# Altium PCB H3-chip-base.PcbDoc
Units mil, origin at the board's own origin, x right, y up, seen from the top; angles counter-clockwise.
Board outline 2027 x 2640 mil, 2 copper layers (Top Layer, Bottom Layer); 10 components, 44 nets, 118 pads, 31 vias.
Unrouted connection lines stored in the file: 24.
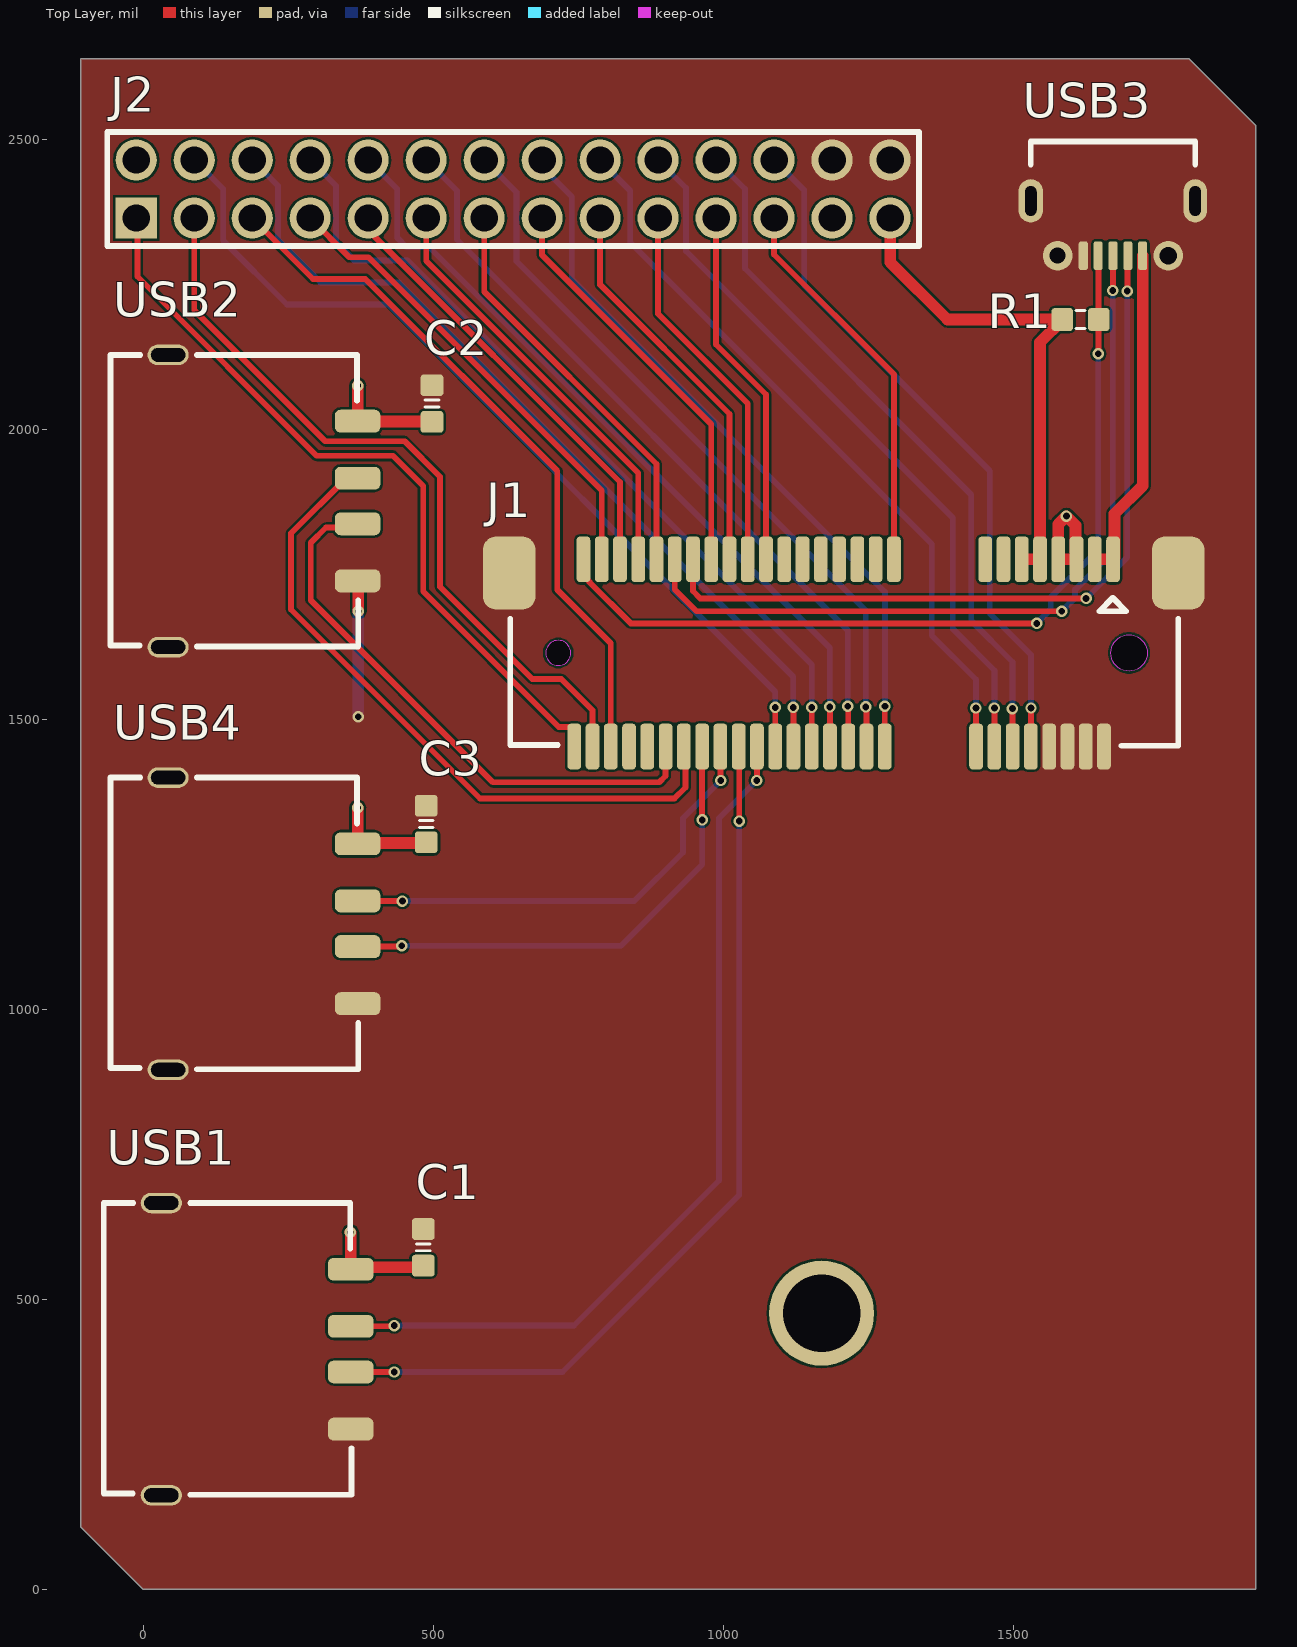
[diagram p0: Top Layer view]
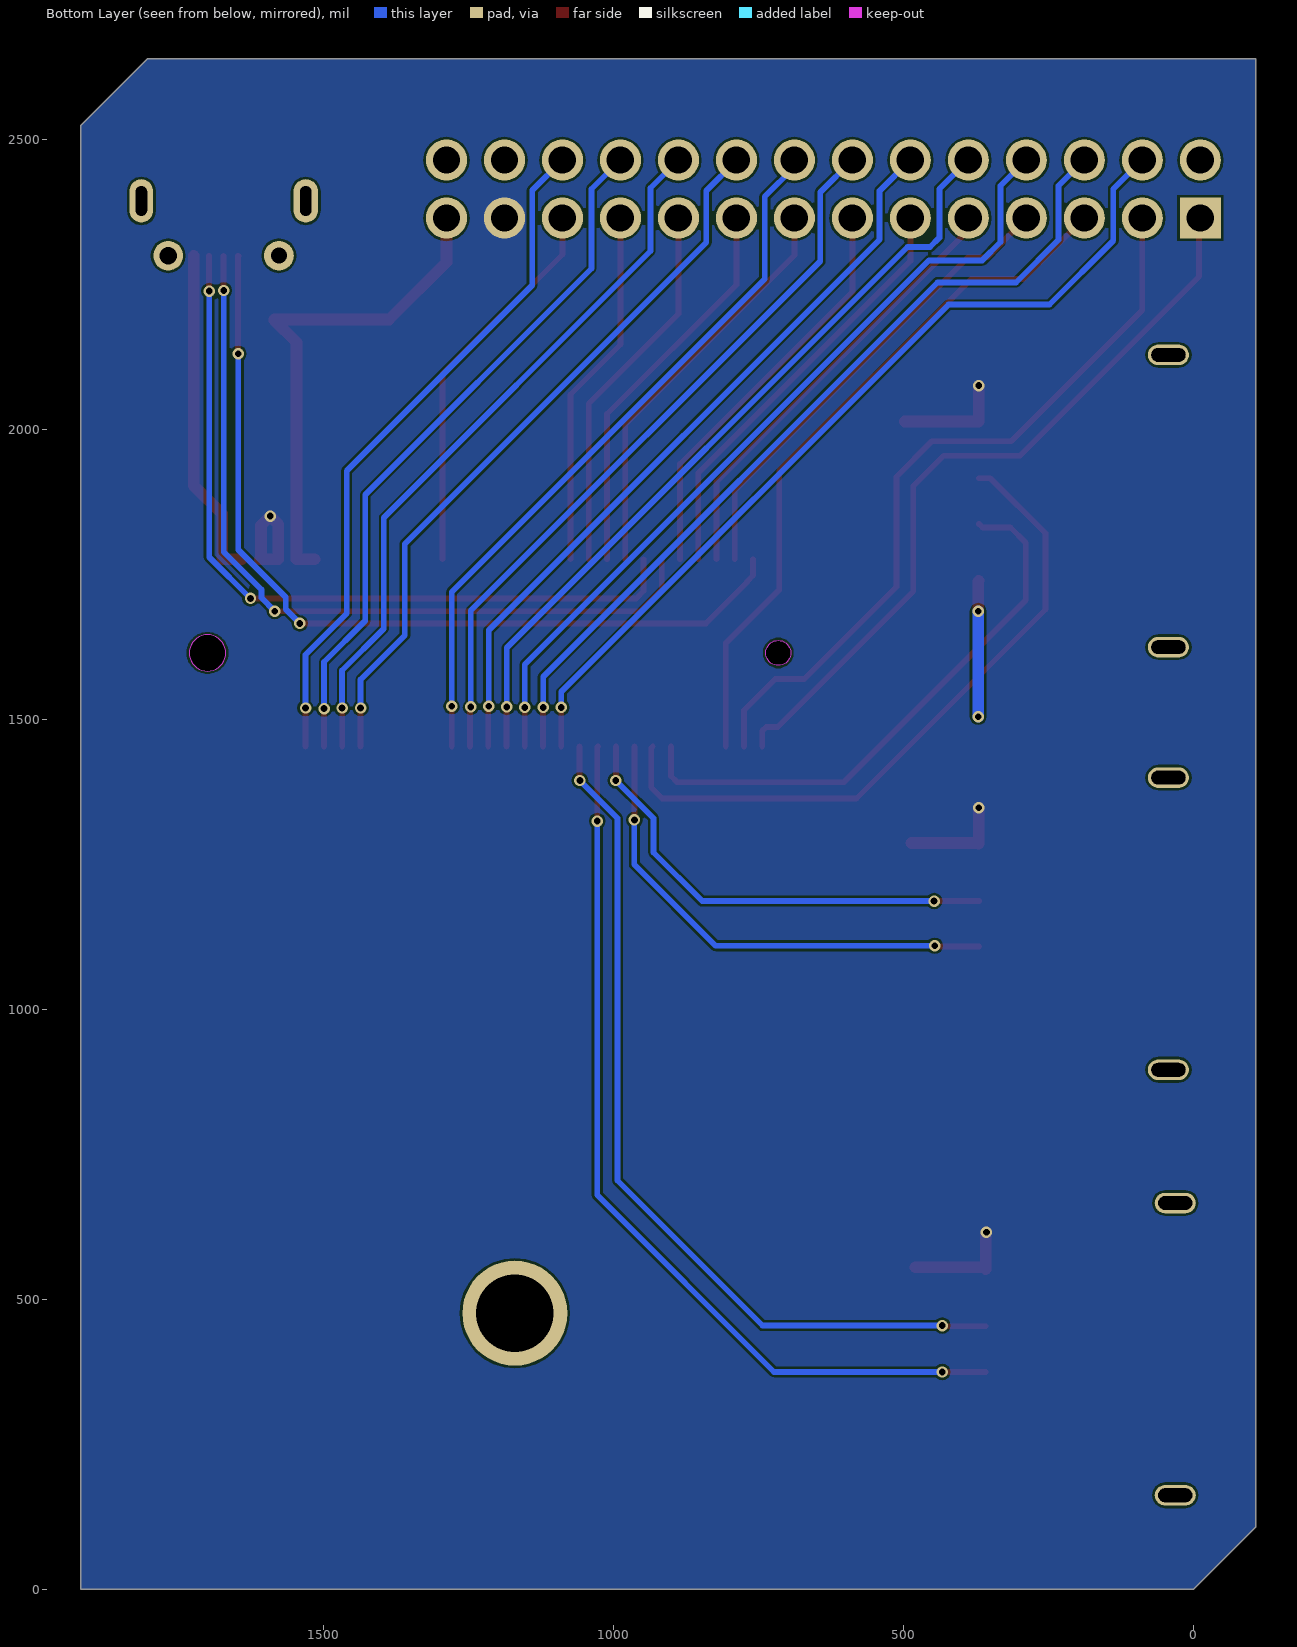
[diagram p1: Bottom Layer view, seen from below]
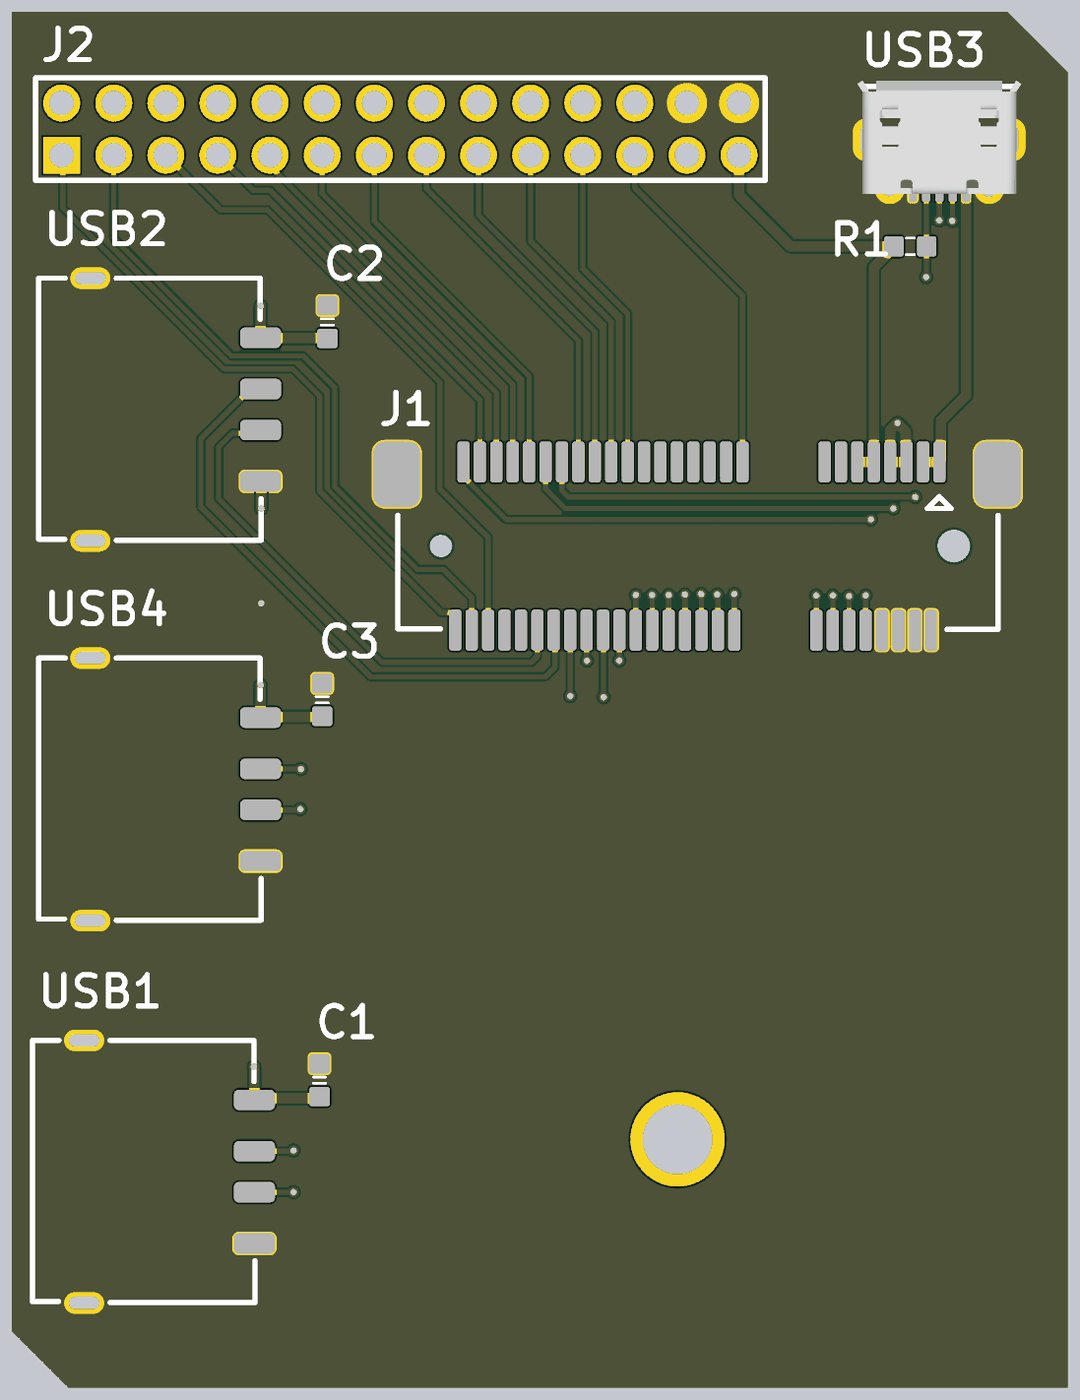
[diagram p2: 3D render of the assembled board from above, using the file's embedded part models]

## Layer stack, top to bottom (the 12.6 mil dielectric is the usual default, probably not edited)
Top Solder: solder mask 0.4, Solder Resist, Dk 3.5
Top Layer: signal copper 1.4
Dielectric 1: dielectric 12.6, FR-4, Dk 4.8
Bottom Layer: signal copper 1.4
Bottom Solder: solder mask 0.4, Solder Resist, Dk 3.5

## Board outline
-108,108 0,0 1919,0 1919,2524 1803,2640 -108,2640

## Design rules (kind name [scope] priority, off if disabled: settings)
Clearance [All] p1: gap=4 ignorepadtopadclearanceinfootprint=FALSE except(0: Arc-Hole Track-Hole SMDPad-Hole THPad-Hole Via-Hole Fill-Hole Poly-Hole Region-Hole Text-Hole)
ComponentClearance [All] p1: gap=0 collisioncheckmode=3 verticalgap=0 showdistances=FALSE
DiffPairsRouting [All] p1: maxlimit=4 minlimit=4 mostfreqgap=4 toplayer_minwidth=4 toplayer_maxwidth=4 toplayer_prefwidth=4 bottomlayer_minwidth=4 bottomlayer_maxwidth=4 bottomlayer_prefwidth=4 maxuncoupledlength=500
FanoutControl Fanout_BGA [All] p1: bgadir=Out bgaviamode=Centered fanoutstyle=Auto fanoutdirection=Alternating viagrid=1 // Fanout_BGA (Default Rule)
HoleSize [All] p1: absolutevalues=TRUE maxlimit=10000 minlimit=8 maxpercent=80.000 minpercent=20.000
MinimumSolderMaskSliver [All] p1 off: minsoldermaskwidth=2
PlaneClearance [All] p1: clearance=8
PlaneConnect [All] p1: planeconnectstyle=Direct reliefexpansion=20 reliefentries=4 reliefconductorwidth=10 reliefairgap=10
PolygonConnect [All] p1: connectstyle=Direct reliefconductorwidth=10 reliefentries=4 polygonreliefangle="90 Angle" airgapwidth=10
RoutingVias [All] p1: holewidth=11.81 width=19.68 viastyle="Through Hole" minholewidth=11.81 minwidth=19.68 maxholewidth=28 maxwidth=50
SilkToSilkClearance [All] p1: silktosilkclearance=0
SilkToSolderMaskClearance [IsPad] p1: minsilkscreentomaskgap=0 clearancetoexposedcopper=TRUE
SolderMaskExpansion [All] p1: expansion=3
Width GND [(InNet('AGND') OR InNet('GND'))] p1: maxlimit=50 minlimit=4 preferedwidth=20
Width VCC [(InNet('VDD_SYS_3.3V') OR InNet('VDD_AV_3.3V') OR InNet('VDD_5V') OR InNet('VDD1V2-SYS') OR InNet('VDD1V1-EPHY') OR InNet('VDD-CPUX') OR InNet('VDD-CPUS') OR InNet('VDD-CPUFB') OR InNet('VCC-DRAM'))] p2: maxlimit=50 minlimit=4 preferedwidth=20
Width [All] p3: maxlimit=10000 minlimit=4 preferedwidth=10
21 further rules are at their usual default settings.

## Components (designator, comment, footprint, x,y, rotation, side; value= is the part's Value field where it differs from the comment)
C1 "22uF" CAP_0603 483,590 r90 top
C2 "22uF" CAP_0603 498,2045 r90 top
C3 "22uF" CAP_0603 488,1320 r90 top
J1 "mini PCI-E座" "mini PCI-E座" 1208,1615 r180 top
J2 "2*14p 2.54mm排针" "2*14p 2.54mm排针" 638,2415 r0 top
R1 "10K" RES_0603 1616.5,2190 r0 top
USB1 "USB typeA座" "USB typeA座" 358,414.37 r270 top
USB2 "USB typeA座" "USB typeA座" 369.77,1876.97 r270 top
USB3 "MicroUSB" MicroUSB 1672.41,2300 r180 top
USB4 "USB typeA座" "USB typeA座" 369.77,1148.03 r270 top

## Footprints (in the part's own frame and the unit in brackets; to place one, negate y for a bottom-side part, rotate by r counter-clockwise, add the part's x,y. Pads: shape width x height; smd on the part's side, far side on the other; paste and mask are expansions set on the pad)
"2*14p 2.54mm排针" [mm] "2*14p 2.54mm排针"
  rect 1.8x1.8 hole 1.2 mask+0.076: 1(-16.51,-1.27)
  round 1.8 hole 1.2 mask+0.076: 2(-16.51,1.27) 3(-13.97,-1.27) 4(-13.97,1.27) 5(-11.43,-1.27) 6(-11.43,1.27) 7(-8.89,-1.27) 8(-8.89,1.27) 9(-6.35,-1.27) 10(-6.35,1.27) 11(-3.81,-1.27) 12(-3.81,1.27) 13(-1.27,-1.27) 14(-1.27,1.27) 15(1.27,-1.27) 16(1.27,1.27) 17(3.81,-1.27) 18(3.81,1.27) 19(6.35,-1.27) 20(6.35,1.27) 21(8.89,-1.27) 22(8.89,1.27) 23(11.43,-1.27) 24(11.43,1.27) 25(13.97,-1.27) 26(13.97,1.27) 27(16.51,-1.27) 28(16.51,1.27)
  silkscreen extent -17.78,-2.5 17.78,2.5, body extent -17.78,-2.54 17.78,2.54, height 8.51
CAP_0603 [mm] "0603 Capacitor"
  rrect30% 0.95x1 smd mask+0.076: 1(-0.8,0) 2(0.8,0)
  silkscreen extent -0.15,-0.3 0.15,0.3
MicroUSB [mm] "MicroUSB"
  oval 1.03x1.9 hole 1.3 slot 0.5 at 0 deg mask+0.076: 0(-3.6,-2.4)
  round 1.3 hole 0.762 mask+0.076: 0(-2.425,0)
  round 1.3 hole 0.7 mask+0.076: 0(2.425,0)
  oval 1.07x1.9 hole 1.3 slot 0.5 at 0 deg mask+0.076: 0(3.6,-2.4)
  rrect50% 0.4x1.25 smd mask+0.076: 1(-1.3,0) 2(-0.65,0) 3(0,0) 4(0.65,0) 5(1.3,0)
  silkscreen extent -3.6,-5 3.6,-4, body extent -4,-5.29 4,0.24, height 2.74
"mini PCI-E座" [mm] "mini PCI-E座"
  rrect50% 0.6x2 smd mask+0.076: 1(-11.8,-4.1) 2(-11.4,4.1) 3(-11,-4.1) 4(-10.6,4.1) 5(-10.2,-4.1) 6(-9.8,4.1) 7(-9.4,-4.1) 8(-9,4.1) 9(-8.6,-4.1) 10(-8.2,4.1) 11(-7.8,-4.1) 12(-7.4,4.1) 13(-7,-4.1) 14(-6.6,4.1) 15(-6.2,-4.1) 16(-5.8,4.1) 17(-2.2,-4.1) 18(-1.8,4.1) 19(-1.4,-4.1) 20(-1,4.1) 21(-0.6,-4.1) 22(-0.2,4.1) 23(0.2,-4.1) 24(0.6,4.1) 25(1,-4.1) 26(1.4,4.1) 27(1.8,-4.1) 28(2.2,4.1) 29(2.6,-4.1) 30(3,4.1) 31(3.4,-4.1) 32(3.8,4.1) 33(4.2,-4.1) 34(4.6,4.1) 35(5,-4.1) 36(5.4,4.1) 37(5.8,-4.1) 38(6.2,4.1) 39(6.6,-4.1) 40(7,4.1) 41(7.4,-4.1) 42(7.8,4.1) 43(8.2,-4.1) 44(8.6,4.1) 45(9,-4.1) 46(9.4,4.1) 47(9.8,-4.1) 48(10.2,4.1) 49(10.6,-4.1) 50(11,4.1) 51(11.4,-4.1) 52(11.8,4.1)
  rrect50% 2.3x3.2 smd: 53(-14.65,-3.5) 54(14.65,-3.5)
  Keep-Out Layer board cut-out: 11.95,0 11.992,-0.21 12.111,-0.389 12.29,-0.508 12.5,-0.55 12.5,-0.55 12.71,-0.508 12.889,-0.389 13.008,-0.21 13.05,0 13.05,0 13.008,0.21 12.889,0.389 12.71,0.508 12.5,0.55 12.5,0.55 12.29,0.508 12.111,0.389 11.992,0.21 11.95,0
  Keep-Out Layer board cut-out: -12.5,-0.8 -12.806,-0.739 -13.066,-0.566 -13.239,-0.306 -13.3,0 -13.3,0 -13.239,0.306 -13.066,0.566 -12.806,0.739 -12.5,0.8 -12.5,0.8 -12.194,0.739 -11.934,0.566 -11.761,0.306 -11.7,0 -11.7,0 -11.761,-0.306 -11.934,-0.566 -12.194,-0.739 -12.5,-0.8
  silkscreen extent -14.66,-2.41 14.6,4.06, body extent -15.03,-5.1 14.97,5.1, height 4.01
RES_0603 [mm] "0603 Resistor"
  rrect30% 0.95x1 smd mask+0.076: 1(-0.8,0) 2(0.8,0)
  silkscreen extent -0.2,-0.4 0.2,0.4
"USB typeA座" [mm] "USB typeA座"
  oval 0.9x1.8 hole 1.5 slot 0.6 at 0 deg mask+0.076: 0(-6.4,-8.3) 0(6.4,-8.3)
  rrect50% 1x2 smd mask+0.076: 1(-3.5,0) 2(-1,0) 3(1,0) 4(3.5,0)
  silkscreen extent -6.4,-10.82 6.38,0.03, body extent -7.3,-10.86 7.3,0.03, height 6.31

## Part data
C1 C2 C3: library part CAP_0603_22uF, "0603"
R1: library part RES_0603_10K, "0603"

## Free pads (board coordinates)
  round 181.1 hole 133.86 mask+3: PAD(1170,476.38)

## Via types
v1: diameter 19.68, hole 11.81, Top Layer to Bottom Layer, tented both sides, 31 vias

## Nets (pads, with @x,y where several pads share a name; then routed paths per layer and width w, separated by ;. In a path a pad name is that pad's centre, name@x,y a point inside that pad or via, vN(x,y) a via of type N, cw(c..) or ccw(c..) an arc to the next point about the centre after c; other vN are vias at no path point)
AP-RESET#: J1.48 J2.5 | length 1220.3
  Top Layer w10: J2.5 293,2260 383,2260 714,1929 714,1724 806.43,1631.57 J1.48
GND: C1.2 C2.2 C3.2 J1.2 J1.4 J1.6 J1.8 J1.53 J1.54 J2.26 J2.28 USB1.0 USB1.4 USB2.0 USB2.4 USB3.0 USB3.5 USB4.0 USB4.4 | length 234.7
  Top Layer w20: USB2.4 371,1737.94 v1(371,1687)
  Bottom Layer w20: v1(371,1505) v1(371,1687)
GPIOA10/STATUS-LED: J1.17 J2.23 | length 674.2
  Top Layer w10: J2.23 1088,2302 1294.61,2095.39 J1.17
GPIOG11: J1.52 J2.1 | length 1313.4
  Top Layer w10: J2.1 -10,2363 -10,2264 299,1955 431,1955 483,1903 483,1721 716.62,1487.38 736.69,1487.38 743.43,1480.64 J1.52
GPIOG12/USB0_OTGID: J1.51 R1.2 USB3.4 | length 1523.6
  Top Layer w10: J1.51 759.18,1748.37 769.87,1737.68 769.87,1736.78 840.64,1666 v1(1541,1666) ; USB3.4 1647.41,2299.41 1647.41,2190.59 R1.2@1647.5,2190.5 ; v1(1647,2131) 1647.5,2131.5 R1.2@1647.5,2190.5 ; R1.2 R1.2@1647.5,2190.5
  Bottom Layer w10: v1(1541,1666) 1565.16,1690.16 1565.16,1711.16 1647,1793 v1(1647,2131)
GPIOL3/K1: J1.49 J2.7 | length 816.1
  Top Layer w10: J2.7 355.5,2297.5 388.5,2297.5 790.68,1895.32 J1.49
GPIOL4/RECOVERY: J1.47 J2.9 | length 768.4
  Top Layer w10: J2.9 388,2344 822.17,1909.83 J1.47
GPIOL10/PWR-LED: J1.45 J2.11 | length 740
  Top Layer w10: J2.11 488,2291 853.67,1925.33 J1.45
GPIOL11/IR-RX: J1.43 J2.13 | length 711.7
  Top Layer w10: J2.13 588,2238 885.17,1940.83 J1.43
I2C0_SCL: J1.20 J2.14 | length 1284.5
  Top Layer w10: v1(1246,1522) 1247.37,1520.63 J1.20
  Bottom Layer w10: J2.14 643.57,2409.43 643.57,2290.43 1246,1688 v1(1246,1522)
I2C0_SDA: J1.18 J2.16 | length 1256.3
  Top Layer w10: J1.18 1278.87,1522.87 v1(1279,1523)
  Bottom Layer w10: J2.16 688,2453 739,2402 739,2260 1279,1720 v1(1279,1523)
RPHY_LINK_LED: J1.29
RPHY_RXN: J1.23
RPHY_RXP: J1.21
RPHY_SPD_LED: J1.19
RPHY_TXN: J1.27
RPHY_TXP: J1.25
SPI0_CLK: J1.12 J2.22 | length 1224.6
  Top Layer w10: v1@1498,1520 v1(1499,1519) 1499.34,1518.66 J1.12
  Bottom Layer w10: J2.22 1038,2415 1038,2278 1428,1888 1428,1670.31 1499,1599.31 v1(1499,1519)
SPI0_CS: J1.10 J2.24 | length 1195
  Top Layer w10: J1.10 1530.83,1519.83 v1(1531,1520)
  Bottom Layer w10: J2.24 1140,2413 1140,2249 1460,1929 1460,1683 1531,1612 v1(1531,1520)
SPI0_MISO: J1.14 J2.20 | length 1251.7
  Top Layer w10: J1.14 1467.84,1519.84 v1(1468,1520)
  Bottom Layer w10: J2.20 936,2417 936,2308 1396,1848 1396,1656.81 1468,1584.81 v1(1468,1520)
SPI0_MOSI: J1.16 J2.18 | length 1280
  Top Layer w10: v1(1436,1520) 1436.35,1519.65 J1.16
  Bottom Layer w10: J2.18 788,2464 840,2412 840,2323 1360,1803 1360,1645 1436,1569 v1(1436,1520)
TV_OUT: J1.30 J2.4 | length 1528.4
  Top Layer w10: J1.30 1089.89,1520.89 v1(1090,1521)
  Bottom Layer w10: J2.4 138,2415 138,2326 248,2216 422,2216 1090,1548 v1(1090,1521)
UART0_RX: J1.44
UART0_TX: J1.46
UART1_CTS: J1.24 J2.10 | length 1364.1
  Top Layer w10: v1(1184,1522) 1184.38,1521.62 J1.24
  Bottom Layer w10: J2.10 438,2415 438,2331 454,2315 493,2315 1184,1624 v1(1184,1522)
UART1_RTS: J1.28 J2.6 | length 1477.1
  Top Layer w10: v1(1121,1521) 1121.39,1520.61 J1.28
  Bottom Layer w10: J2.6 232.43,2420.57 232.43,2327.57 306,2254 441,2254 1121,1574 v1(1121,1521)
UART1_RX: J1.26 J2.8 | length 1423.7
  Top Layer w10: J1.26 1152.88,1520.88 v1(1153,1521)
  Bottom Layer w10: J2.8 332.43,2420.57 332.43,2323.57 364,2292 456,2292 1153,1595 v1(1153,1521)
UART1_TX: J1.22 J2.12 | length 1312.9
  Top Layer w10: v1(1215,1523) 1215.87,1522.13 J1.22
  Bottom Layer w10: J2.12 541,2412 541,2328 1215,1654 v1(1215,1523)
UART2_CTS: J1.31 J2.21 | length 624.3
  Top Layer w10: J2.21 988,2147 1074.14,2060.86 J1.31
UART2_RTS: J1.35 J2.17 | length 681
  Top Layer w10: J2.17 788,2250 1011.15,2026.85 J1.35
UART2_RX: J1.37 J2.15 | length 709.4
  Top Layer w10: J2.15 688,2301 979.65,2009.35 J1.37
UART2_TX: J1.33 J2.19 | length 652.6
  Top Layer w10: J2.19 888,2200 1042.65,2045.35 J1.33
UBOOT: J1.50 J2.3 | length 1305.5
  Top Layer w10: J2.3 88,2206 314,1980 451,1980 512,1919 512,1729 671,1570 721,1570 774.93,1516.07 J1.50
USB_DM0: J1.39 USB3.2 | length 1358.7
  Top Layer w10: J1.39 948.16,1721.62 960.78,1709 v1(1626,1709) ; v1(1697,2239) 1697.5,2239.5 1697.5,2299.5 USB3.2
  Bottom Layer w10: v1(1626,1709) 1697,1780 v1(1697,2239)
USB_DM1: J1.40 USB2.2 | length 1180
  Top Layer w10: USB2.2 350.09,1916.34 255,1821.25 255,1690 581,1364 916,1364 935,1383 935,1450.99 J1.40
USB_DM2: J1.36 USB4.2 | length 805.9
  Top Layer w10: USB4.2 446.6,1187.4 v1(447,1187) ; J1.36 995.4,1395.6 v1(996,1395)
  Bottom Layer w10: v1(447,1187) 847,1187 931,1271 931,1330 v1(996,1395)
USB_DM3: J1.32 USB1.2 | length 1514.7
  Top Layer w10: USB1.2 431.74,453.74 v1(433,455) ; v1(1058,1395) 1058.39,1395.39 J1.32
  Bottom Layer w10: v1(433,455) 743,455 993,705 993,1330 v1(1058,1395)
USB_DP0: J1.41 USB3.3 | length 1384.5
  Top Layer w10: J1.41 916.66,1724.34 954,1687 v1(1584,1687) ; v1(1672,2240) 1672.41,2240.41 USB3.3
  Bottom Layer w10: v1(1584,1687) 1607.16,1710.16 1607.16,1724.16 1672,1789 v1(1672,2240)
USB_DP1: J1.42 USB2.3 | length 990.5
  Top Layer w10: USB2.3 363.57,1831.4 315.4,1831.4 289,1805 289,1706 603,1392 890.06,1392 900.91,1402.86 J1.42
USB_DP2: J1.38 USB4.3 | length 856.4
  Top Layer w10: USB4.3 442.66,1108.66 444,1110 v1(446,1110) ; J1.38 963.91,1327.09 v1(964,1327)
  Bottom Layer w10: v1(446,1110) 824,1110 964,1250 v1(964,1327)
USB_DP3: J1.34 USB1.3 | length 1570.4
  Top Layer w10: USB1.3 v1(433,375) ; J1.34 1028,1452.48 v1(1028,1325)
  Bottom Layer w10: v1(433,375) 723,375 1028,680 v1(1028,1325)
VDD_5V: C1.1 C2.1 C3.1 J1.5 J1.7 J2.25 USB1.1 USB2.1 USB4.1 | length 757.3
  Top Layer w10: USB1.1 USB1.1@361.17,555.33 ; USB4.1 USB4.1@371.11,1287.17 ; USB2.1 USB2.1@370.4,2014.13 ; C1.1@479.83,555.33 C1.1 ; C3.1@486.66,1287.17 C3.1 ; C2.1@497.37,2014.13 C2.1
  Top Layer w20: v1(357,616) 358,615 USB1.1 ; USB1.1@361.17,555.33 C1.1@479.83,555.33 ; USB4.1 369.77,1347.77 v1(370,1348) ; USB2.1 369.77,2075.77 v1(370,2076) ; USB2.1@370.4,2014.13 C2.1@497.37,2014.13 ; USB4.1@371.11,1287.17 C3.1@486.66,1287.17 ; J1.7 1578.08,1837.08 v1(1592,1851) 1607.76,1835.24 1607.76,1778.23 J1.5 J1.7
VDD_SYS_3.3V: J1.9 J1.11 J2.27 R1.1 | length 875
  Top Layer w20: J2.27 1288,2289 1387,2190 R1.1 1585.01,2189.02 1546.58,2150.59 J1.9 J1.11
VDD_USB_5V: J1.1 J1.3 USB3.1 | length 576.2
  Top Layer w20: J1.3 J1.1 1675,1778.85 1675,1855 1723.59,1903.59 USB3.1
pads on no net: J1.13 J1.15 J2.2

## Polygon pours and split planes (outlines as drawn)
GND on Top Layer "GND_L01_P000" (solid, pour order 0): -108,108 0,0 1919,0 1919,2524 1803,2640 -108,2640
VDD_5V on Bottom Layer "VDD_5V_L02_P001" (solid, pour order 1): -108,108 0,0 1919,0 1919,2524 1803,2640 -108,2640

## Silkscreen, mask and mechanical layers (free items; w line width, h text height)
Mechanical 1:
  the board outline again, w10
